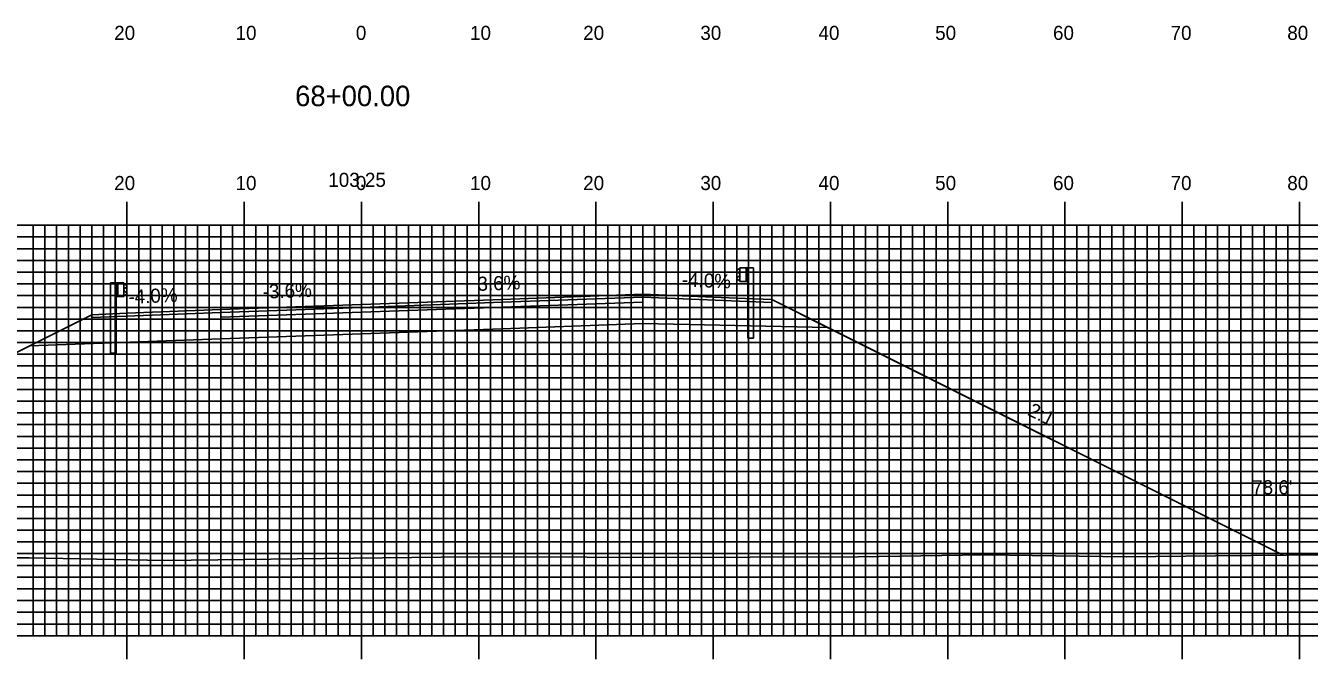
# Model space of a CAD drawing. Extents: x 1759430 to 1759773, y 442591 to 442811.
# Drawn here: x 1759567 to 1759676.5, y 442666.7 to 442720.7 of the extents above; entities that cross this region are included whole.
import ezdxf

# ---------------------------------------------------------------- set-up
doc = ezdxf.new("R2010")
doc.units = 0
for name, color, linetype in [('ANNOTATION', 7, 'Continuous'), ('D_Guardrail_Beam_Lt', 7, 'Continuous'), ('D_Guardrail_Beam_Rt', 7, 'Continuous'), ('D_Roadway_Centerline', 7, 'Continuous'), ('D_Roadway_Centerline_Text', 7, 'Continuous'), ('D_Roadway_Edge_Shoulder', 7, 'Continuous'), ('D_Roadway_Edge_TW', 7, 'Continuous'), ('D_Roadway_Pavement', 7, 'Continuous'), ('D_Roadway_SlopeLines', 7, 'Continuous'), ('D_Roadway_SubGrade', 7, 'Continuous'), ('D_Text_Standard', 7, 'Continuous'), ('H_V ANNOTATION', 7, 'Continuous'), ('MAJOR', 7, 'Continuous'), ('MINOR', 7, 'Continuous'), ('S_Roadway_Centerline', 7, 'Continuous')]:
    doc.layers.add(name, color=color, linetype=linetype)

msp = doc.modelspace()

# ---------------------------------------------------------------- linework, layer by layer
at = {"layer": 'D_Guardrail_Beam_Lt'}
for p, q in [((1759574.25, 442698.75), (1759574.25, 442692.75)), ((1759574.72, 442698.75), (1759574.25, 442698.75)), ((1759575.4, 442698.75), (1759574.72, 442698.75)), ((1759574.72, 442698.75), (1759574.72, 442697.58)), ((1759574.78, 442698.75), (1759574.78, 442697.58)), ((1759574.88, 442698.75), (1759574.88, 442697.58)), ((1759575.4, 442697.58), (1759575.4, 442698.75)), ((1759575.4, 442698.66), (1759575.48, 442698.65)), ((1759575.41, 442698.2), (1759575.41, 442698.13)), ((1759575.64, 442698.4), (1759575.44, 442698.26)), ((1759575.49, 442698.64), (1759575.64, 442698.54)), ((1759574.72, 442697.58), (1759575.4, 442697.58)), ((1759574.74, 442692.75), (1759574.74, 442697.58)), ((1759575.48, 442697.68), (1759575.4, 442697.66)), ((1759575.44, 442698.06), (1759575.64, 442697.93)), ((1759575.64, 442697.78), (1759575.49, 442697.68)), ((1759574.74, 442692.75), (1759574.25, 442692.75))]:
    msp.add_line(p, q, dxfattribs=at)
for centre, major_axis, start_param, end_param in [((1759575.49, 442698.2), (-0.0789, 0), 5.323254, 6.283185), ((1759575.47, 442698.61), (0.0417, 0), 0.959931, 1.376053), ((1759575.59, 442698.47), (0.0877, 0), 5.323254, 7.243116), ((1759575.49, 442698.13), (-0.0789, 0), 6.283185, 7.243116), ((1759575.47, 442697.72), (0.0417, 0), 4.907132, 5.323254), ((1759575.59, 442697.86), (0.0877, 0), 5.323254, 7.243116)]:
    msp.add_ellipse(centre, major_axis=major_axis, ratio=0.995501, start_param=start_param, end_param=end_param, dxfattribs=at)
at = {"layer": 'D_Guardrail_Beam_Rt'}
for p, q in [((1759627.86, 442699.94), (1759627.71, 442699.84)), ((1759627.71, 442699.69), (1759627.91, 442699.56)), ((1759627.91, 442699.36), (1759627.71, 442699.22)), ((1759627.95, 442699.96), (1759627.87, 442699.94)), ((1759627.94, 442699.49), (1759627.94, 442699.42)), ((1759627.95, 442700.04), (1759628.63, 442700.04)), ((1759627.95, 442698.88), (1759627.95, 442700.04)), ((1759628.47, 442700.04), (1759628.47, 442698.88)), ((1759628.57, 442700.04), (1759628.57, 442698.88)), ((1759628.63, 442700.04), (1759629.1, 442700.04)), ((1759628.63, 442700.04), (1759628.63, 442698.88)), ((1759629.1, 442700.04), (1759629.1, 442694.04)), ((1759627.71, 442699.08), (1759627.86, 442698.98)), ((1759627.87, 442698.97), (1759627.95, 442698.96)), ((1759628.63, 442698.88), (1759627.95, 442698.88)), ((1759628.61, 442694.04), (1759628.61, 442698.88)), ((1759628.61, 442694.04), (1759629.1, 442694.04))]:
    msp.add_line(p, q, dxfattribs=at)
for centre, major_axis, start_param, end_param in [((1759627.76, 442699.77), (-0.0877, 0), 5.323254, 7.243116), ((1759627.88, 442699.9), (-0.0417, 0), 4.907132, 5.323254), ((1759627.86, 442699.49), (0.0789, 0), 0, 0.959931), ((1759627.86, 442699.42), (0.0789, 0), 5.323254, 6.283185), ((1759627.76, 442699.15), (-0.0877, 0), 5.323254, 7.243116), ((1759627.88, 442699.01), (-0.0417, 0), 0.959931, 1.376053)]:
    msp.add_ellipse(centre, major_axis=major_axis, ratio=0.995501, start_param=start_param, end_param=end_param, dxfattribs=at)
at = {"layer": 'D_Roadway_Centerline'}
msp.add_lwpolyline([(1759530.46, 442674.94), (1759567.38, 442693.4), (1759572.67, 442696.04), (1759575.67, 442696.16), (1759583.67, 442696.48), (1759595.67, 442696.91), (1759607.67, 442697.35), (1759619.67, 442697.78), (1759627.67, 442697.46), (1759630.67, 442697.34), (1759635.42, 442694.96), (1759674.27, 442675.54)], dxfattribs=at)
at = {"layer": 'D_Roadway_Edge_Shoulder'}
for points in [[(1759619.67, 442697.78), (1759627.67, 442697.46), (1759627.67, 442697.46), (1759630.67, 442697.34), (1759630.67, 442697.09), (1759619.67, 442697.53)], [(1759583.67, 442696.48), (1759575.67, 442696.16), (1759575.67, 442696.16), (1759572.67, 442696.04), (1759572.67, 442695.79), (1759583.67, 442696.23)]]:
    msp.add_lwpolyline(points, close=True, dxfattribs=at)
at = {"layer": 'D_Roadway_Edge_TW'}
for points in [[(1759583.67, 442696.23), (1759583.67, 442696.48), (1759595.67, 442696.91), (1759607.67, 442697.35), (1759607.67, 442697.1), (1759595.67, 442696.66)], [(1759607.67, 442697.35), (1759619.67, 442697.78), (1759619.67, 442697.53), (1759607.67, 442697.1)]]:
    msp.add_lwpolyline(points, close=True, dxfattribs=at)
at = {"layer": 'D_Roadway_Pavement'}
for points in [[(1759583.67, 442695.82), (1759583.67, 442696.23), (1759595.67, 442696.66), (1759607.67, 442697.1), (1759607.67, 442696.68), (1759595.67, 442696.25)], [(1759607.67, 442697.1), (1759619.67, 442697.53), (1759619.67, 442697.11), (1759607.67, 442696.68)]]:
    msp.add_lwpolyline(points, close=True, dxfattribs=at)
for points in [[(1759619.67, 442697.53), (1759619.67, 442697.11)], [(1759619.67, 442697.53), (1759619.67, 442697.11)], [(1759583.67, 442696.23), (1759583.67, 442695.82)]]:
    msp.add_lwpolyline(points, dxfattribs=at)
at = {"layer": 'D_Roadway_SlopeLines'}
for points in [[(1759630.67, 442697.34), (1759674.27, 442675.54)], [(1759572.67, 442696.04), (1759530.46, 442674.94)]]:
    msp.add_lwpolyline(points, dxfattribs=at)
at = {"layer": 'D_Roadway_SubGrade'}
for points in [[(1759607.67, 442696.68), (1759619.67, 442697.11), (1759619.67, 442695.28), (1759607.67, 442694.85)], [(1759619.67, 442697.11), (1759619.67, 442697.53), (1759630.67, 442697.09), (1759630.67, 442697.34), (1759635.42, 442694.96), (1759619.67, 442695.28)], [(1759583.67, 442695.82), (1759583.67, 442696.23), (1759572.67, 442695.79), (1759572.67, 442696.04), (1759567.38, 442693.4), (1759583.67, 442693.98)], [(1759583.67, 442693.98), (1759583.67, 442695.82), (1759595.67, 442696.25), (1759607.67, 442696.68), (1759607.67, 442694.85), (1759595.67, 442694.41)]]:
    msp.add_lwpolyline(points, close=True, dxfattribs=at)
at = {"layer": 'MAJOR'}
for p, q in [((1759575.67, 442705.67), (1759575.67, 442703.67)), ((1759585.67, 442705.67), (1759585.67, 442703.67)), ((1759595.67, 442705.67), (1759595.67, 442703.67)), ((1759605.67, 442705.67), (1759605.67, 442703.67)), ((1759615.67, 442705.67), (1759615.67, 442703.67)), ((1759625.67, 442705.67), (1759625.67, 442703.67)), ((1759635.67, 442705.67), (1759635.67, 442703.67)), ((1759645.67, 442705.67), (1759645.67, 442703.67)), ((1759655.67, 442705.67), (1759655.67, 442703.67)), ((1759665.67, 442705.67), (1759665.67, 442703.67)), ((1759675.67, 442705.67), (1759675.67, 442703.67)), ((1759455.67, 442703.67), (1759735.67, 442703.67)), ((1759455.67, 442703.67), (1759735.67, 442703.67)), ((1759575.67, 442668.67), (1759575.67, 442703.67)), ((1759585.67, 442668.67), (1759585.67, 442703.67)), ((1759595.67, 442668.67), (1759595.67, 442703.67)), ((1759605.67, 442668.67), (1759605.67, 442703.67)), ((1759615.67, 442668.67), (1759615.67, 442703.67)), ((1759625.67, 442668.67), (1759625.67, 442703.67)), ((1759635.67, 442668.67), (1759635.67, 442703.67)), ((1759645.67, 442668.67), (1759645.67, 442703.67)), ((1759655.67, 442668.67), (1759655.67, 442703.67)), ((1759665.67, 442668.67), (1759665.67, 442703.67)), ((1759675.67, 442668.67), (1759675.67, 442703.67)), ((1759455.67, 442698.67), (1759735.67, 442698.67)), ((1759455.67, 442693.67), (1759735.67, 442693.67)), ((1759455.67, 442688.67), (1759735.67, 442688.67)), ((1759455.67, 442683.67), (1759735.67, 442683.67)), ((1759455.67, 442678.67), (1759735.67, 442678.67)), ((1759455.67, 442673.67), (1759735.67, 442673.67)), ((1759455.67, 442668.67), (1759735.67, 442668.67)), ((1759455.67, 442668.67), (1759735.67, 442668.67)), ((1759575.67, 442666.66), (1759575.67, 442668.67)), ((1759585.67, 442666.66), (1759585.67, 442668.67)), ((1759595.67, 442666.66), (1759595.67, 442668.67)), ((1759605.67, 442666.66), (1759605.67, 442668.67)), ((1759615.67, 442666.66), (1759615.67, 442668.67)), ((1759625.67, 442666.66), (1759625.67, 442668.67)), ((1759635.67, 442666.66), (1759635.67, 442668.67)), ((1759645.67, 442666.66), (1759645.67, 442668.67)), ((1759655.67, 442666.66), (1759655.67, 442668.67)), ((1759665.67, 442666.66), (1759665.67, 442668.67)), ((1759675.67, 442666.66), (1759675.67, 442668.67))]:
    msp.add_line(p, q, dxfattribs=at)
at = {"layer": 'MINOR'}
for p, q in [((1759567.67, 442668.67), (1759567.67, 442703.67)), ((1759568.67, 442668.67), (1759568.67, 442703.67)), ((1759569.67, 442668.67), (1759569.67, 442703.67)), ((1759570.67, 442668.67), (1759570.67, 442703.67)), ((1759571.67, 442668.67), (1759571.67, 442703.67)), ((1759572.67, 442668.67), (1759572.67, 442703.67)), ((1759573.67, 442668.67), (1759573.67, 442703.67)), ((1759574.67, 442668.67), (1759574.67, 442703.67)), ((1759576.67, 442668.67), (1759576.67, 442703.67)), ((1759577.67, 442668.67), (1759577.67, 442703.67)), ((1759578.67, 442668.67), (1759578.67, 442703.67)), ((1759579.67, 442668.67), (1759579.67, 442703.67)), ((1759580.67, 442668.67), (1759580.67, 442703.67)), ((1759581.67, 442668.67), (1759581.67, 442703.67)), ((1759582.67, 442668.67), (1759582.67, 442703.67)), ((1759583.67, 442668.67), (1759583.67, 442703.67)), ((1759584.67, 442668.67), (1759584.67, 442703.67)), ((1759586.67, 442668.67), (1759586.67, 442703.67)), ((1759587.67, 442668.67), (1759587.67, 442703.67)), ((1759588.67, 442668.67), (1759588.67, 442703.67)), ((1759589.67, 442668.67), (1759589.67, 442703.67)), ((1759590.67, 442668.67), (1759590.67, 442703.67)), ((1759591.67, 442668.67), (1759591.67, 442703.67)), ((1759592.67, 442668.67), (1759592.67, 442703.67)), ((1759593.67, 442668.67), (1759593.67, 442703.67)), ((1759594.67, 442668.67), (1759594.67, 442703.67)), ((1759596.67, 442668.67), (1759596.67, 442703.67)), ((1759597.67, 442668.67), (1759597.67, 442703.67)), ((1759598.67, 442668.67), (1759598.67, 442703.67)), ((1759599.67, 442668.67), (1759599.67, 442703.67)), ((1759600.67, 442668.67), (1759600.67, 442703.67)), ((1759601.67, 442668.67), (1759601.67, 442703.67)), ((1759602.67, 442668.67), (1759602.67, 442703.67)), ((1759603.67, 442668.67), (1759603.67, 442703.67)), ((1759604.67, 442668.67), (1759604.67, 442703.67)), ((1759606.67, 442668.67), (1759606.67, 442703.67)), ((1759607.67, 442668.67), (1759607.67, 442703.67)), ((1759608.67, 442668.67), (1759608.67, 442703.67)), ((1759609.67, 442668.67), (1759609.67, 442703.67)), ((1759610.67, 442668.67), (1759610.67, 442703.67)), ((1759611.67, 442668.67), (1759611.67, 442703.67)), ((1759612.67, 442668.67), (1759612.67, 442703.67)), ((1759613.67, 442668.67), (1759613.67, 442703.67)), ((1759614.67, 442668.67), (1759614.67, 442703.67)), ((1759616.67, 442668.67), (1759616.67, 442703.67)), ((1759617.67, 442668.67), (1759617.67, 442703.67)), ((1759618.67, 442668.67), (1759618.67, 442703.67)), ((1759619.67, 442668.67), (1759619.67, 442703.67)), ((1759620.67, 442668.67), (1759620.67, 442703.67)), ((1759621.67, 442668.67), (1759621.67, 442703.67)), ((1759622.67, 442668.67), (1759622.67, 442703.67)), ((1759623.67, 442668.67), (1759623.67, 442703.67)), ((1759624.67, 442668.67), (1759624.67, 442703.67)), ((1759626.67, 442668.67), (1759626.67, 442703.67)), ((1759627.67, 442668.67), (1759627.67, 442703.67)), ((1759628.67, 442668.67), (1759628.67, 442703.67)), ((1759629.67, 442668.67), (1759629.67, 442703.67)), ((1759630.67, 442668.67), (1759630.67, 442703.67)), ((1759631.67, 442668.67), (1759631.67, 442703.67)), ((1759632.67, 442668.67), (1759632.67, 442703.67)), ((1759633.67, 442668.67), (1759633.67, 442703.67)), ((1759634.67, 442668.67), (1759634.67, 442703.67)), ((1759636.67, 442668.67), (1759636.67, 442703.67)), ((1759637.67, 442668.67), (1759637.67, 442703.67)), ((1759638.67, 442668.67), (1759638.67, 442703.67)), ((1759639.67, 442668.67), (1759639.67, 442703.67)), ((1759640.67, 442668.67), (1759640.67, 442703.67)), ((1759641.67, 442668.67), (1759641.67, 442703.67)), ((1759642.67, 442668.67), (1759642.67, 442703.67)), ((1759643.67, 442668.67), (1759643.67, 442703.67)), ((1759644.67, 442668.67), (1759644.67, 442703.67)), ((1759646.67, 442668.67), (1759646.67, 442703.67)), ((1759647.67, 442668.67), (1759647.67, 442703.67)), ((1759648.67, 442668.67), (1759648.67, 442703.67)), ((1759649.67, 442668.67), (1759649.67, 442703.67)), ((1759650.67, 442668.67), (1759650.67, 442703.67)), ((1759651.67, 442668.67), (1759651.67, 442703.67)), ((1759652.67, 442668.67), (1759652.67, 442703.67)), ((1759653.67, 442668.67), (1759653.67, 442703.67)), ((1759654.67, 442668.67), (1759654.67, 442703.67)), ((1759656.67, 442668.67), (1759656.67, 442703.67)), ((1759657.67, 442668.67), (1759657.67, 442703.67)), ((1759658.67, 442668.67), (1759658.67, 442703.67)), ((1759659.67, 442668.67), (1759659.67, 442703.67)), ((1759660.67, 442668.67), (1759660.67, 442703.67)), ((1759661.67, 442668.67), (1759661.67, 442703.67)), ((1759662.67, 442668.67), (1759662.67, 442703.67)), ((1759663.67, 442668.67), (1759663.67, 442703.67)), ((1759664.67, 442668.67), (1759664.67, 442703.67)), ((1759666.67, 442668.67), (1759666.67, 442703.67)), ((1759667.67, 442668.67), (1759667.67, 442703.67)), ((1759668.67, 442668.67), (1759668.67, 442703.67)), ((1759669.67, 442668.67), (1759669.67, 442703.67)), ((1759670.67, 442668.67), (1759670.67, 442703.67)), ((1759671.67, 442668.67), (1759671.67, 442703.67)), ((1759672.67, 442668.67), (1759672.67, 442703.67)), ((1759673.67, 442668.67), (1759673.67, 442703.67)), ((1759674.67, 442668.67), (1759674.67, 442703.67)), ((1759455.67, 442702.67), (1759735.67, 442702.67)), ((1759455.67, 442701.67), (1759735.67, 442701.67)), ((1759455.67, 442700.67), (1759735.67, 442700.67)), ((1759455.67, 442699.67), (1759735.67, 442699.67)), ((1759455.67, 442697.67), (1759735.67, 442697.67)), ((1759455.67, 442696.67), (1759735.67, 442696.67)), ((1759455.67, 442695.67), (1759735.67, 442695.67)), ((1759455.67, 442694.67), (1759735.67, 442694.67)), ((1759455.67, 442692.67), (1759735.67, 442692.67)), ((1759455.67, 442691.67), (1759735.67, 442691.67)), ((1759455.67, 442690.67), (1759735.67, 442690.67)), ((1759455.67, 442689.67), (1759735.67, 442689.67)), ((1759455.67, 442687.67), (1759735.67, 442687.67)), ((1759455.67, 442686.67), (1759735.67, 442686.67)), ((1759455.67, 442685.67), (1759735.67, 442685.67)), ((1759455.67, 442684.67), (1759735.67, 442684.67)), ((1759455.67, 442682.67), (1759735.67, 442682.67)), ((1759455.67, 442681.67), (1759735.67, 442681.67)), ((1759455.67, 442680.67), (1759735.67, 442680.67)), ((1759455.67, 442679.67), (1759735.67, 442679.67)), ((1759455.67, 442677.67), (1759735.67, 442677.67)), ((1759455.67, 442676.67), (1759735.67, 442676.67)), ((1759455.67, 442675.67), (1759735.67, 442675.67)), ((1759455.67, 442674.67), (1759735.67, 442674.67)), ((1759455.67, 442672.67), (1759735.67, 442672.67)), ((1759455.67, 442671.67), (1759735.67, 442671.67)), ((1759455.67, 442670.67), (1759735.67, 442670.67)), ((1759455.67, 442669.67), (1759735.67, 442669.67))]:
    msp.add_line(p, q, dxfattribs=at)
at = {"layer": 'S_Roadway_Centerline'}
msp.add_lwpolyline([(1759564.25, 442675.3), (1759567.34, 442675.32), (1759578.88, 442675.09), (1759592.48, 442675.26), (1759602.47, 442675.37), (1759608.85, 442675.39), (1759620.96, 442675.34), (1759628.82, 442675.37), (1759638.04, 442675.4), (1759648.72, 442675.56), (1759648.87, 442675.56), (1759660.89, 442675.39), (1759668.52, 442675.47), (1759677.56, 442675.58), (1759689.56, 442675.67), (1759704.69, 442675.71), (1759710.29, 442675.71), (1759720.18, 442675.79), (1759730.72, 442675.79), (1759734.55, 442675.78), (1759735.67, 442675.79)], dxfattribs=at)

# ---------------------------------------------------------------- texts
at = {"layer": 'ANNOTATION'}
for s, rotation, p in [('3.6%', 2.0618, (1759605.58, 442698.07)), ('-4.0%', 357.7094, (1759622.97, 442698.45)), ('-4.0%', 2.2906, (1759575.81, 442696.97)), ('-3.6%', 2.0618, (1759587.26, 442697.41)), ('2:1', 333.4349, (1759652.41, 442687.51))]:
    msp.add_text(s, height=1.2, rotation=rotation, dxfattribs=at).set_placement(p)
at = {"layer": 'D_Roadway_Centerline'}
for s in ['C', 'L']:
    msp.add_text(s, height=0.0146, dxfattribs=at).set_placement((1759595.67, 442696.91))
at = {"layer": 'D_Roadway_Centerline_Text'}
msp.add_text('103.25', height=1.2, dxfattribs=at).set_placement((1759592.84, 442706.94))
at = {"layer": 'D_Text_Standard'}
msp.add_text("78.6'", height=1.2, dxfattribs=at).set_placement((1759671.64, 442680.73))
at = {"layer": 'H_V ANNOTATION'}
for s, height, p in [('20', 1.2, (1759574.58, 442719.47)), ('10', 1.2, (1759584.93, 442719.47)), ('0', 1.2, (1759595.19, 442719.47)), ('10', 1.2, (1759604.93, 442719.47)), ('20', 1.2, (1759614.58, 442719.47)), ('30', 1.2, (1759624.57, 442719.47)), ('40', 1.2, (1759634.65, 442719.47)), ('50', 1.2, (1759644.6, 442719.47)), ('60', 1.2, (1759654.65, 442719.47)), ('70', 1.2, (1759664.68, 442719.47)), ('80', 1.2, (1759674.63, 442719.47)), ('68+00.00', 1.75, (1759590.01, 442713.82)), ('20', 1.2, (1759574.58, 442706.67)), ('10', 1.2, (1759584.93, 442706.67)), ('0', 1.2, (1759595.19, 442706.67)), ('10', 1.2, (1759604.93, 442706.67)), ('20', 1.2, (1759614.58, 442706.67)), ('30', 1.2, (1759624.57, 442706.67)), ('40', 1.2, (1759634.65, 442706.67)), ('50', 1.2, (1759644.6, 442706.67)), ('60', 1.2, (1759654.65, 442706.67)), ('70', 1.2, (1759664.68, 442706.67)), ('80', 1.2, (1759674.63, 442706.67))]:
    msp.add_text(s, height=height, dxfattribs=at).set_placement(p)

doc.saveas('drawing.dxf')
